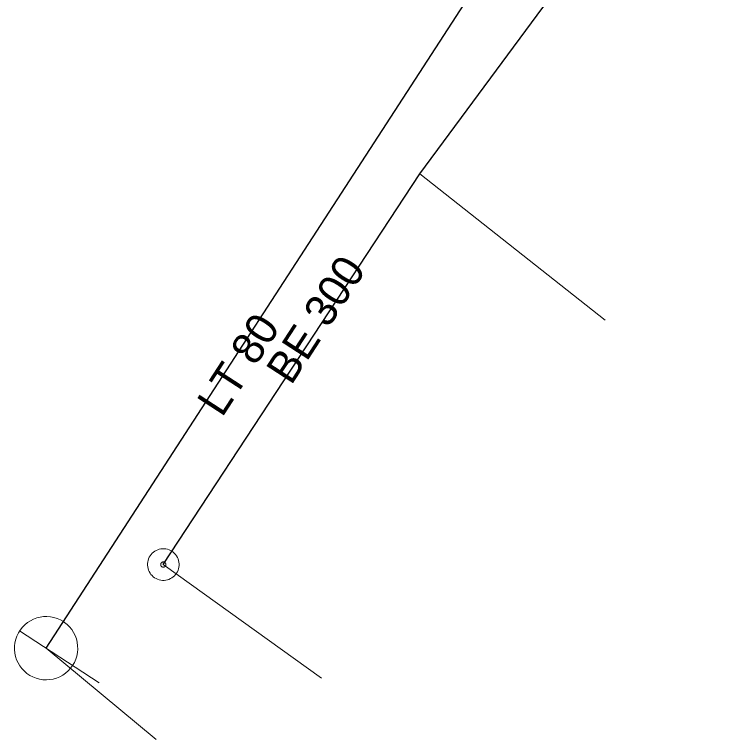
# Model space of a CAD drawing. Extents: x -791337 to -790755, y -988454 to -987923.
# Drawn here: x -791065.12 to -791042.21, y -988089.35 to -988066.45 of the extents above; entities that cross this region are included whole.
import ezdxf

# ---------------------------------------------------------------- set-up
doc = ezdxf.new("R2010")
doc.units = 0
doc.header["$LTSCALE"] = 0.4
for name, color, linetype, lineweight in [('1', 7, 'Continuous', 13), ('11', 7, 'Continuous', 13), ('13', 7, 'Continuous', 13), ('14', 7, 'Continuous', 25), ('17', 7, 'Continuous', 25), ('22', 7, 'Continuous', 13), ('47', 7, 'Continuous', 13)]:
    doc.layers.add(name, color=color, linetype=linetype, lineweight=lineweight)

msp = doc.modelspace()

# ---------------------------------------------------------------- linework, layer by layer
at = {"layer": '11'}
msp.add_line((-791060.636, -988089.35), (-791064.119, -988086.467), dxfattribs=at)
at = {"layer": '13'}
for p, q in [((-791052.313, -988071.484), (-791046.456, -988076.107)), ((-791060.415, -988083.824), (-791055.418, -988087.416))]:
    msp.add_line(p, q, dxfattribs=at)
at = {"layer": '14'}
msp.add_line((-791064.119, -988086.467), (-791048.694, -988062.718), dxfattribs=at)
at = {"layer": '17'}
msp.add_lwpolyline([(-791060.415, -988083.824), (-791052.313, -988071.484), (-791043.758, -988059.914), (-791042.206, -988056.414), (-791045.877, -988047.25), (-791044.421, -988045.406)], dxfattribs=at)
at = {"layer": '22'}
msp.add_line((-791062.441, -988087.556), (-791064.957, -988085.922), dxfattribs=at)
msp.add_lwpolyline([(-791063.573, -988085.628), (-791063.668, -988085.574), (-791063.768, -988085.53), (-791063.874, -988085.497), (-791063.98, -988085.476), (-791064.09, -988085.467), (-791064.199, -988085.47), (-791064.308, -988085.485), (-791064.414, -988085.512), (-791064.517, -988085.55), (-791064.614, -988085.598), (-791064.706, -988085.658), (-791064.791, -988085.728), (-791064.868, -988085.806), (-791064.936, -988085.892), (-791064.994, -988085.985), (-791065.041, -988086.083), (-791065.078, -988086.186), (-791065.103, -988086.293), (-791065.116, -988086.402), (-791065.117, -988086.511), (-791065.106, -988086.62), (-791065.084, -988086.727), (-791065.049, -988086.832), (-791065.004, -988086.931), (-791064.948, -988087.025), (-791064.882, -988087.112), (-791064.806, -988087.192), (-791064.723, -988087.263), (-791064.632, -988087.324), (-791064.535, -988087.375), (-791064.434, -988087.416), (-791064.328, -988087.444), (-791064.22, -988087.462), (-791064.111, -988087.467), (-791064.001, -988087.46), (-791063.894, -988087.441), (-791063.788, -988087.411), (-791063.687, -988087.369), (-791063.591, -988087.317), (-791063.501, -988087.254), (-791063.419, -988087.182), (-791063.345, -988087.101), (-791063.28, -988087.012), (-791063.226, -988086.918), (-791063.182, -988086.817), (-791063.149, -988086.713), (-791063.128, -988086.606), (-791063.119, -988086.496), (-791063.122, -988086.387), (-791063.136, -988086.278), (-791063.162, -988086.172), (-791063.201, -988086.069), (-791063.249, -988085.971), (-791063.309, -988085.88), (-791063.378, -988085.795), (-791063.456, -988085.717), (-791063.542, -988085.65)], close=True, dxfattribs=at)
at = {"layer": '47'}
for points in [[(-791060.14, -988083.406), (-791060.185, -988083.38), (-791060.233, -988083.358), (-791060.283, -988083.342), (-791060.333, -988083.33), (-791060.386, -988083.324), (-791060.439, -988083.324), (-791060.49, -988083.33), (-791060.541, -988083.341), (-791060.591, -988083.356), (-791060.639, -988083.377), (-791060.685, -988083.403), (-791060.727, -988083.434), (-791060.766, -988083.468), (-791060.801, -988083.507), (-791060.832, -988083.549), (-791060.858, -988083.594), (-791060.88, -988083.642), (-791060.897, -988083.692), (-791060.908, -988083.742), (-791060.914, -988083.795), (-791060.914, -988083.848), (-791060.908, -988083.9), (-791060.898, -988083.951), (-791060.883, -988084.001), (-791060.861, -988084.048), (-791060.835, -988084.094), (-791060.804, -988084.137), (-791060.77, -988084.175), (-791060.731, -988084.21), (-791060.689, -988084.241), (-791060.644, -988084.267), (-791060.596, -988084.289), (-791060.546, -988084.306), (-791060.496, -988084.317), (-791060.443, -988084.323), (-791060.391, -988084.323), (-791060.339, -988084.318), (-791060.287, -988084.308), (-791060.237, -988084.292), (-791060.19, -988084.27), (-791060.144, -988084.244), (-791060.102, -988084.214), (-791060.063, -988084.179), (-791060.028, -988084.14), (-791059.997, -988084.098), (-791059.971, -988084.053), (-791059.949, -988084.005), (-791059.932, -988083.956), (-791059.921, -988083.905), (-791059.915, -988083.852), (-791059.915, -988083.8), (-791059.92, -988083.748), (-791059.931, -988083.697), (-791059.947, -988083.647), (-791059.968, -988083.599), (-791059.994, -988083.553), (-791060.024, -988083.512), (-791060.059, -988083.472), (-791060.098, -988083.437)], [(-791060.369, -988083.755), (-791060.377, -988083.75), (-791060.385, -988083.747), (-791060.393, -988083.745), (-791060.401, -988083.743), (-791060.41, -988083.742), (-791060.418, -988083.742), (-791060.427, -988083.742), (-791060.435, -988083.744), (-791060.443, -988083.747), (-791060.451, -988083.75), (-791060.459, -988083.755), (-791060.466, -988083.76), (-791060.472, -988083.765), (-791060.478, -988083.771), (-791060.483, -988083.778), (-791060.488, -988083.786), (-791060.491, -988083.794), (-791060.493, -988083.802), (-791060.495, -988083.81), (-791060.496, -988083.819), (-791060.496, -988083.827), (-791060.496, -988083.836), (-791060.494, -988083.844), (-791060.491, -988083.853), (-791060.488, -988083.86), (-791060.483, -988083.868), (-791060.478, -988083.875), (-791060.473, -988083.881), (-791060.467, -988083.887), (-791060.46, -988083.892), (-791060.452, -988083.897), (-791060.444, -988083.9), (-791060.436, -988083.902), (-791060.428, -988083.904), (-791060.419, -988083.905), (-791060.411, -988083.906), (-791060.402, -988083.905), (-791060.394, -988083.903), (-791060.385, -988083.9), (-791060.378, -988083.897), (-791060.37, -988083.892), (-791060.363, -988083.887), (-791060.357, -988083.882), (-791060.351, -988083.876), (-791060.346, -988083.869), (-791060.341, -988083.861), (-791060.338, -988083.853), (-791060.336, -988083.845), (-791060.334, -988083.837), (-791060.333, -988083.828), (-791060.332, -988083.82), (-791060.333, -988083.811), (-791060.335, -988083.803), (-791060.338, -988083.795), (-791060.341, -988083.787), (-791060.346, -988083.779), (-791060.351, -988083.772), (-791060.356, -988083.766), (-791060.362, -988083.76)]]:
    msp.add_lwpolyline(points, close=True, dxfattribs=at)

# ---------------------------------------------------------------- texts
at = {"layer": '1'}
for s, p in [('BE 300', (-791056.375, -988078.19)), ('LT 80 ', (-791058.559, -988079.203))]:
    msp.add_text(s, height=1, rotation=57, dxfattribs=at).set_placement(p)

doc.saveas('drawing.dxf')
